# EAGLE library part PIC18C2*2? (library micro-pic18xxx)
High-Performance Microcontrollers with 10-Bit A/D
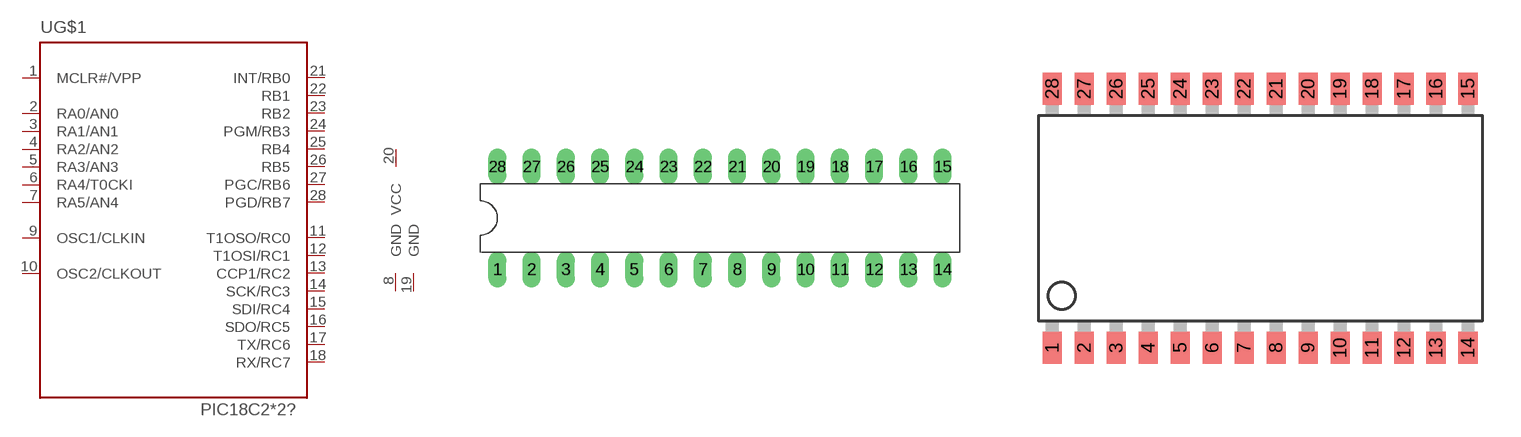
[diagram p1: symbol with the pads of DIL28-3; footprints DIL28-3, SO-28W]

Designator prefix -; gates G$1=ABC G$2=VDD G$3=VSS G$4=VSS

## PIC18C242SP, PIC18C252SP  [DIL28-3]
1  G$1:MCLR#/VPP  in
2  G$1:RA0/AN0
3  G$1:RA1/AN1
4  G$1:RA2/AN2
5  G$1:RA3/AN3
6  G$1:RA4/T0CKI
7  G$1:RA5/AN4
8  G$3:GND  pwr
9  G$1:OSC1/CLKIN  in
10  G$1:OSC2/CLKOUT  out
11  G$1:T1OSO/RC0
12  G$1:T1OSI/RC1
13  G$1:CCP1/RC2
14  G$1:SCK/RC3
15  G$1:SDI/RC4
16  G$1:SDO/RC5
17  G$1:TX/RC6
18  G$1:RX/RC7
19  G$4:GND  pwr
20  G$2:VCC  pwr
21  G$1:INT/RB0
22  G$1:RB1
23  G$1:RB2
24  G$1:PGM/RB3
25  G$1:RB4
26  G$1:RB5
27  G$1:PGC/RB6
28  G$1:PGD/RB7

## PIC18C242SO, PIC18C252SO  [SO-28W]
Pads as for DIL28-3

## Footprint DIL28-3 (pad centres in mm)
DIL package type P
drill 0.813 long: 1 -16.51,-3.81; 2 -13.97,-3.81; 3 -11.43,-3.81; 4 -8.89,-3.81; 5 -6.35,-3.81; 6 -3.81,-3.81; 7 -1.27,-3.81; 8 1.27,-3.81; 9 3.81,-3.81; 10 6.35,-3.81; 11 8.89,-3.81; 12 11.43,-3.81; 13 13.97,-3.81; 14 16.51,-3.81; 15 16.51,3.81; 16 13.97,3.81; 17 11.43,3.81; 18 8.89,3.81; 19 6.35,3.81; 20 3.81,3.81; 21 1.27,3.81; 22 -1.27,3.81; 23 -3.81,3.81; 24 -6.35,3.81; 25 -8.89,3.81; 26 -11.43,3.81; 27 -13.97,3.81; 28 -16.51,3.81

## Footprint SO-28W (pad centres in mm)
Small Outline Wide Plastic Gull Wing 300-mil body package type SO
smd 0.762 x 1.27: 1 -7.62,-5.207; 2 -6.35,-5.207; 3 -5.08,-5.207; 4 -3.81,-5.207; 5 -2.54,-5.207; 6 -1.27,-5.207; 7 0,-5.207; 8 1.27,-5.207; 9 2.54,-5.207; 10 3.81,-5.207; 11 5.08,-5.207; 12 6.35,-5.207; 13 7.62,-5.207; 14 8.89,-5.207; 15 8.89,5.08; 16 7.62,5.08; 17 6.35,5.08; 18 5.08,5.08; 19 3.81,5.08; 20 2.54,5.08; 21 1.27,5.08; 22 0,5.08; 23 -1.27,5.08; 24 -2.54,5.08; 25 -3.81,5.08; 26 -5.08,5.08; 27 -6.35,5.08; 28 -7.62,5.08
